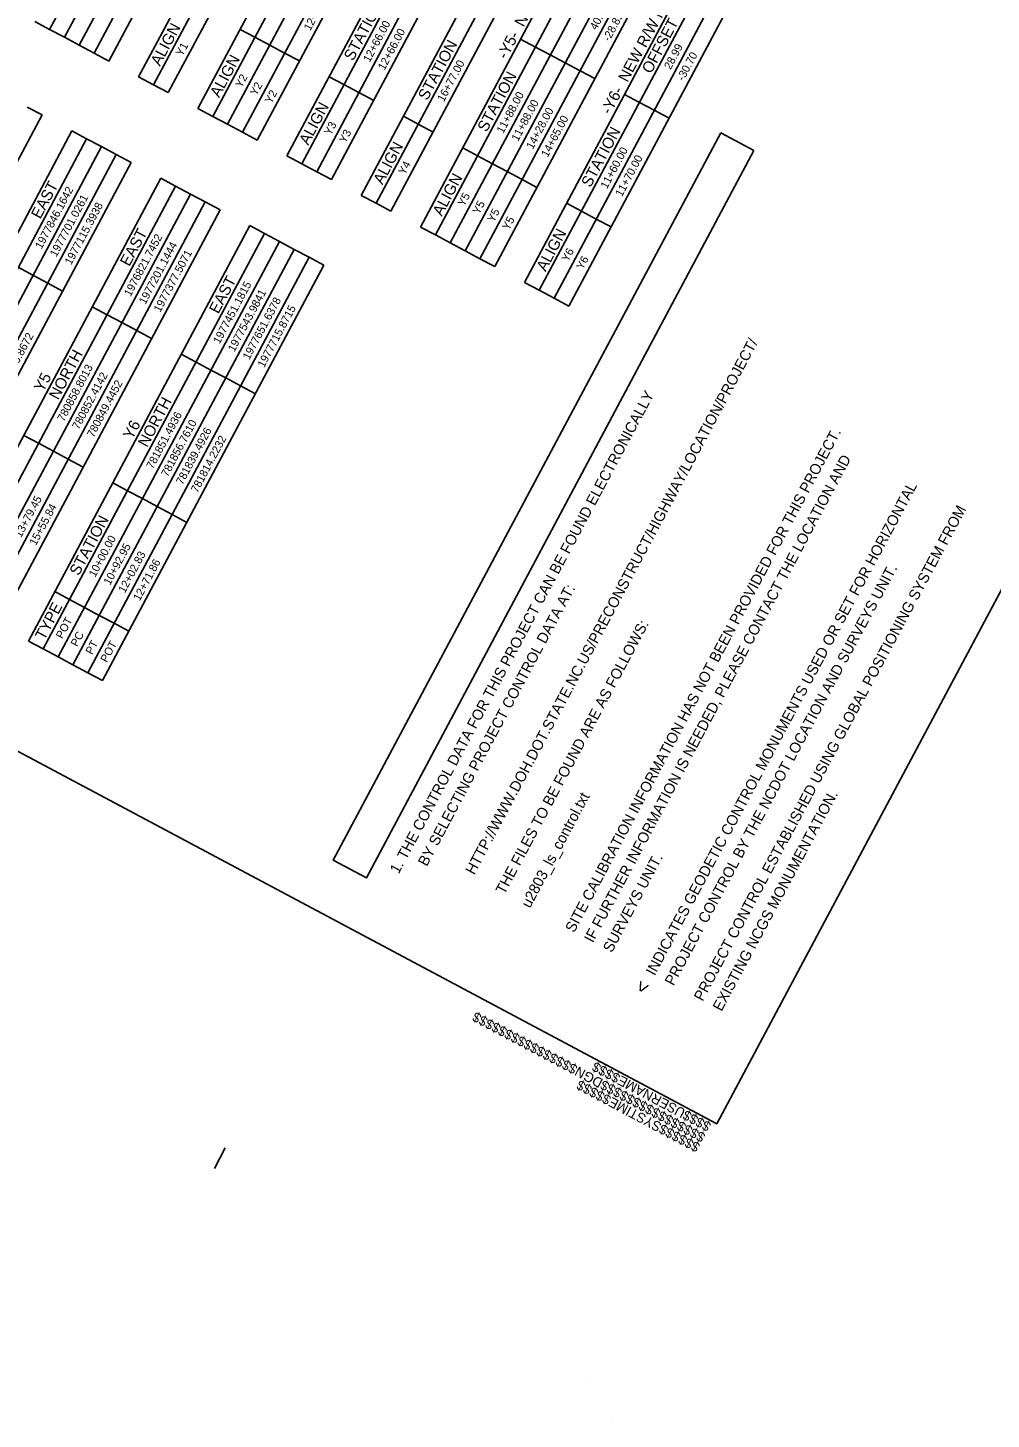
# Model space of a CAD drawing. Extents: x 1979034 to 1987549, y 771535 to 781988.
# Drawn here: x 1981933 to 1984640, y 771535 to 775446 of the extents above; entities that cross this region are included whole.
import ezdxf

# ---------------------------------------------------------------- set-up
doc = ezdxf.new("R2010")
doc.units = 0
for name, color, linetype in [('CTL Sheet Border CELL', 7, 'Continuous'), ('CTL Sheet Notes CELL', 7, 'Continuous'), ('CTL Sheet Table Cell', 7, 'Continuous'), ('CTL Sheet Text', 7, 'Continuous'), ('Old_Level_2', 7, 'Continuous'), ('Old_Level_57', 7, 'Continuous'), ('Sheet Data Field CELL', 7, 'Continuous')]:
    doc.layers.add(name, color=color, linetype=linetype)

msp = doc.modelspace()

# ---------------------------------------------------------------- linework, layer by layer
at = {"layer": 'CTL Sheet Border CELL'}
msp.add_lwpolyline([(1982714.7, 781848.1), (1979034.2, 774941.4), (1983868.8, 772365.1), (1987549.3, 779271.7)], close=True, dxfattribs=at)
for points in [[(1983973.6, 775100.4), (1982884.2, 773056), (1982790.5, 773105.7), (1983880, 775150.2)], [(1983880, 775150.2), (1983973.6, 775100.4)]]:
    msp.add_lwpolyline(points, dxfattribs=at)
at = {"layer": 'CTL Sheet Table Cell'}
for p, q in [((1981993.9, 775441.2), (1982823.5, 776997.9)), ((1982035.6, 775418.9), (1982865.2, 776975.7)), ((1982077.3, 775396.7), (1982906.9, 776953.5)), ((1982119, 775374.5), (1982948.6, 776931.3)), ((1982160.7, 775352.3), (1982990.3, 776909)), ((1982244.1, 775307.8), (1983073.7, 776864.6)), ((1982285.8, 775285.6), (1983115.4, 776842.4)), ((1982327.5, 775263.4), (1983157.1, 776820.1)), ((1982410.9, 775218.9), (1983240.5, 776775.7)), ((1982452.6, 775196.7), (1983282.2, 776753.5)), ((1982494.3, 775174.5), (1983323.9, 776731.3)), ((1982536, 775152.3), (1983365.5, 776709)), ((1982577.7, 775130.1), (1983407.2, 776686.8)), ((1982661.1, 775085.6), (1983490.6, 776642.4)), ((1982702.8, 775063.4), (1983532.3, 776620.2)), ((1982744.5, 775041.2), (1983574, 776597.9)), ((1982786.2, 775019), (1983615.7, 776575.7)), ((1982869.6, 774974.5), (1983699.1, 776531.3)), ((1982911.3, 774952.3), (1983740.8, 776509.1)), ((1982953, 774930.1), (1983782.5, 776486.8)), ((1983036.3, 774885.6), (1983865.9, 776442.4)), ((1983078, 774863.4), (1983907.6, 776420.2)), ((1983119.7, 774841.2), (1983949.3, 776397.9)), ((1983161.4, 774819), (1983991, 776375.7)), ((1983203.1, 774796.7), (1984032.7, 776353.5)), ((1983244.8, 774774.5), (1984074.4, 776331.3)), ((1983328.2, 774730.1), (1984157.8, 776286.8)), ((1983369.9, 774707.9), (1984199.5, 776264.6)), ((1983411.6, 774685.6), (1984241.2, 776242.4)), ((1983453.3, 774663.4), (1984282.9, 776220.2)), ((1981952.2, 775463.4), (1981993.9, 775441.2)), ((1981993.9, 775441.2), (1982035.6, 775418.9)), ((1982035.6, 775418.9), (1982077.3, 775396.7)), ((1982529.4, 775441.3), (1982571.1, 775419.1)), ((1982571.1, 775419.1), (1982612.8, 775396.9)), ((1982077.3, 775396.7), (1982119, 775374.5)), ((1982612.8, 775396.9), (1982654.5, 775374.7)), ((1983317.8, 775413.8), (1983359.5, 775391.6)), ((1983359.5, 775391.6), (1983401.2, 775369.4)), ((1982119, 775374.5), (1982160.7, 775352.3)), ((1982654.5, 775374.7), (1982696.2, 775352.5)), ((1983401.2, 775369.4), (1983442.9, 775347.2)), ((1983442.9, 775347.2), (1983484.6, 775324.9)), ((1982244.1, 775307.8), (1982285.8, 775285.6)), ((1982779.6, 775308), (1982821.3, 775285.8)), ((1983484.6, 775324.9), (1983526.3, 775302.7)), ((1982285.8, 775285.6), (1982327.5, 775263.4)), ((1982821.3, 775285.8), (1982863, 775263.6)), ((1982863, 775263.6), (1982904.7, 775241.4)), ((1981931, 775222.8), (1981972.7, 775200.6)), ((1983609.7, 775258.3), (1983651.4, 775236)), ((1983651.4, 775236), (1983693.1, 775213.8)), ((1981350.6, 774033), (1981972.7, 775200.6)), ((1982410.9, 775218.9), (1982452.6, 775196.7)), ((1982452.6, 775196.7), (1982494.3, 775174.5)), ((1982988.1, 775196.9), (1983029.8, 775174.7)), ((1983693.1, 775213.8), (1983734.8, 775191.6)), ((1981434, 773988.6), (1982056.1, 775156.1)), ((1982056.1, 775156.1), (1982097.8, 775133.9)), ((1982494.3, 775174.5), (1982536, 775152.3)), ((1982536, 775152.3), (1982577.7, 775130.1)), ((1983029.8, 775174.7), (1983071.5, 775152.5)), ((1981475.7, 773966.3), (1982097.8, 775133.9)), ((1981517.4, 773944.1), (1982139.5, 775111.7)), ((1982097.8, 775133.9), (1982139.5, 775111.7)), ((1982139.5, 775111.7), (1982181.2, 775089.5)), ((1983154.9, 775108), (1983196.6, 775085.8)), ((1981559.1, 773921.9), (1982181.2, 775089.5)), ((1981600.8, 773899.7), (1982222.9, 775067.2)), ((1982181.2, 775089.5), (1982222.9, 775067.2)), ((1982661.1, 775085.6), (1982702.8, 775063.4)), ((1983196.6, 775085.8), (1983238.3, 775063.6)), ((1982702.8, 775063.4), (1982744.5, 775041.2)), ((1982744.5, 775041.2), (1982786.2, 775019)), ((1983238.3, 775063.6), (1983280, 775041.4)), ((1983280, 775041.4), (1983321.7, 775019.1)), ((1981684.1, 773855.2), (1982306.3, 775022.8)), ((1981725.8, 773833), (1982348, 775000.6)), ((1982306.3, 775022.8), (1982348, 775000.6)), ((1982348, 775000.6), (1982389.7, 774978.4)), ((1983321.7, 775019.1), (1983363.4, 774996.9)), ((1981767.5, 773810.8), (1982389.7, 774978.4)), ((1981809.2, 773788.6), (1982431.4, 774956.1)), ((1982389.7, 774978.4), (1982431.4, 774956.1)), ((1982431.4, 774956.1), (1982473.1, 774933.9)), ((1982869.6, 774974.5), (1982911.3, 774952.3)), ((1982911.3, 774952.3), (1982953, 774930.1)), ((1983446.8, 774952.5), (1983488.5, 774930.3)), ((1981850.9, 773766.3), (1982473.1, 774933.9)), ((1983488.5, 774930.3), (1983530.2, 774908)), ((1983530.2, 774908), (1983571.8, 774885.8)), ((1981934.3, 773721.9), (1982556.5, 774889.5)), ((1982556.5, 774889.5), (1982598.2, 774867.2)), ((1983036.3, 774885.6), (1983078, 774863.4)), ((1981976, 773699.7), (1982598.2, 774867.2)), ((1982017.7, 773677.5), (1982639.9, 774845)), ((1982598.2, 774867.2), (1982639.9, 774845)), ((1982639.9, 774845), (1982681.6, 774822.8)), ((1983078, 774863.4), (1983119.7, 774841.2)), ((1983119.7, 774841.2), (1983161.4, 774819)), ((1982059.4, 773655.2), (1982681.6, 774822.8)), ((1982101.1, 773633), (1982723.3, 774800.6)), ((1982681.6, 774822.8), (1982723.3, 774800.6)), ((1982723.3, 774800.6), (1982765, 774778.4)), ((1983161.4, 774819), (1983203.1, 774796.7)), ((1983203.1, 774796.7), (1983244.8, 774774.5)), ((1981905.3, 774772.5), (1981947, 774750.3)), ((1982142.8, 773610.8), (1982765, 774778.4)), ((1981947, 774750.3), (1981988.7, 774728.1)), ((1981988.7, 774728.1), (1982030.4, 774705.8)), ((1983328.2, 774730.1), (1983369.9, 774707.9)), ((1983369.9, 774707.9), (1983411.6, 774685.6)), ((1983411.6, 774685.6), (1983453.3, 774663.4)), ((1982113.8, 774661.4), (1982155.5, 774639.2)), ((1982155.5, 774639.2), (1982197.2, 774617)), ((1982197.2, 774617), (1982238.9, 774594.7)), ((1982238.9, 774594.7), (1982280.5, 774572.5)), ((1982363.9, 774528.1), (1982405.6, 774505.9)), ((1982405.6, 774505.9), (1982447.3, 774483.6)), ((1982447.3, 774483.6), (1982489, 774461.4)), ((1982489, 774461.4), (1982530.7, 774439.2)), ((1982530.7, 774439.2), (1982572.4, 774417)), ((1981921.2, 774300), (1981962.9, 774277.8)), ((1981962.9, 774277.8), (1982004.6, 774255.6)), ((1982004.6, 774255.6), (1982046.3, 774233.4)), ((1982046.3, 774233.4), (1982088, 774211.1)), ((1982171.4, 774166.7), (1982213.1, 774144.5)), ((1982213.1, 774144.5), (1982254.8, 774122.2)), ((1982254.8, 774122.2), (1982296.5, 774100)), ((1982296.5, 774100), (1982338.2, 774077.8)), ((1982338.2, 774077.8), (1982379.9, 774055.6)), ((1982008.4, 773860.9), (1982050.1, 773838.7)), ((1982050.1, 773838.7), (1982091.8, 773816.5)), ((1982091.8, 773816.5), (1982133.5, 773794.2)), ((1982133.5, 773794.2), (1982175.2, 773772)), ((1982175.2, 773772), (1982216.9, 773749.8)), ((1981934.3, 773721.9), (1981976, 773699.7)), ((1981976, 773699.7), (1982017.7, 773677.5)), ((1982017.7, 773677.5), (1982059.4, 773655.2)), ((1982059.4, 773655.2), (1982101.1, 773633)), ((1982101.1, 773633), (1982142.8, 773610.8))]:
    msp.add_line(p, q, dxfattribs=at)
at = {"layer": 'Sheet Data Field CELL'}
for p, q in [((1982456.9, 772239.6), (1982487.6, 772297.1)), ((1983502.7, 771649.7), (1983502.7, 771649.7)), ((1983574.1, 771534.8), (1983574.1, 771534.8))]:
    msp.add_line(p, q, dxfattribs=at)

# ---------------------------------------------------------------- texts
at = {"layer": 'CTL Sheet Notes CELL'}
for s, p in [('-Y5-  NEW R/W MONUMENTS', (1983277.6, 775355.1)), ('-Y6-  NEW R/W MONUMENTS', (1983569.5, 775199.6)), ('STATION', (1982846.8, 775350.5)), ('ALIGN', (1982303.8, 775336.2)), ('OFFSET', (1983684.3, 775314.5)), ('STATION', (1983055.3, 775239.4)), ('ALIGN', (1982470.6, 775247.3)), ('STATION', (1983222.1, 775150.5)), ('ALIGN', (1982720.8, 775113.9)), ('STATION', (1983514, 774994.9)), ('ALIGN', (1982929.3, 775002.8)), ('ALIGN', (1983096.1, 774914)), ('EAST', (1981967.7, 774906.3)), ('EAST', (1982217.8, 774773)), ('ALIGN', (1983388, 774758.4)), ('EAST', (1982468, 774639.7)), ('NORTH', (1982017.9, 774397.8)), ('Y5', (1981976, 774419.7)), ('NORTH', (1982268.1, 774264.5)), ('Y6', (1982226.2, 774286.4)), ('STATION', (1982075.6, 773903.3)), ('TYPE', (1981979.2, 773722.3))]:
    msp.add_text(s, height=31.5, rotation=61.9471, dxfattribs=at).set_placement(p)
at = {"layer": 'CTL Sheet Text'}
for s, p in [('12+84.24', (1982726.5, 775435.7)), ('40.00', (1983530.7, 775437.7)), ('12+66.00', (1982893.3, 775346.8)), ('-28.89', (1983567.1, 775405.6)), ('12+66.00', (1982935, 775324.6)), ('Y1', (1982367.1, 775364)), ('28.99', (1983739.2, 775326.6)), ('16+77.00', (1983101.8, 775235.7)), ('-30.70', (1983775.6, 775294.5)), ('Y2', (1982533.9, 775275.1)), ('Y2', (1982575.6, 775252.9)), ('Y2', (1982617.2, 775230.7)), ('11+88.00', (1983268.6, 775146.8)), ('11+88.00', (1983310.3, 775124.6)), ('14+28.00', (1983352, 775102.3)), ('Y3', (1982784, 775141.8)), ('14+65.00', (1983393.7, 775080.1)), ('Y3', (1982825.7, 775119.6)), ('11+60.00', (1983560.5, 774991.2)), ('Y4', (1982992.5, 775030.7)), ('11+70.00', (1983602.2, 774969)), ('1977846.1642', (1981971.1, 774821.9)), ('1977701.0261', (1982012.8, 774799.7)), ('1977115.3938', (1982054.5, 774777.4)), ('Y5', (1983159.3, 774941.8)), ('Y5', (1983201, 774919.6)), ('Y5', (1983242.7, 774897.3)), ('Y5', (1983284.4, 774875.1)), ('1976821.7452', (1982221.3, 774688.6)), ('1977201.1444', (1982263, 774666.3)), ('1977377.5071', (1982304.7, 774644.1)), ('Y6', (1983451.2, 774786.2)), ('Y6', (1983492.9, 774764)), ('1977451.1815', (1982471.5, 774555.2)), ('1977543.9841', (1982513.2, 774533)), ('1977651.6378', (1982554.9, 774510.8)), ('1977715.8715', (1982596.6, 774488.6)), ('780286.8672', (1981867.2, 774425.9)), ('780858.8013', (1982033.9, 774337)), ('780852.4142', (1982075.6, 774314.8)), ('780849.4452', (1982117.3, 774292.6)), ('781851.4936', (1982284.1, 774203.7)), ('781856.7610', (1982325.8, 774181.5)), ('781839.4926', (1982367.5, 774159.3)), ('781814.2232', (1982409.2, 774137)), ('13+79.45', (1981913.6, 774010.8)), ('15+55.84', (1981955.3, 773988.5)), ('10+00.00', (1982122.1, 773899.7)), ('10+92.95', (1982163.8, 773877.4)), ('12+02.83', (1982205.5, 773855.2)), ('12+71.86', (1982247.2, 773833)), ('POT', (1982029.9, 773726.5)), ('PC ', (1982071.6, 773704.3)), ('PT ', (1982113.3, 773682.1)), ('POT', (1982155, 773659.8))]:
    msp.add_text(s, height=22.5, rotation=61.9471, dxfattribs=at).set_placement(p)
at = {"layer": 'Old_Level_2'}
for s, rotation, p in [('HTTP://WWW.DOH.DOT.STATE.NC.US/PRECONSTRUCT/HIGHWAY/LOCATION/PROJECT/', 61.9471, (1983187.1, 773063.1)), ('1. THE CONTROL DATA FOR THIS PROJECT CAN BE FOUND ELECTRONICALLY', 61.9471, (1982974.8, 773065.6)), ('SITE CALIBRATION INFORMATION HAS NOT BEEN PROVIDED FOR THIS PROJECT.', 61.9471, (1983467.9, 772900.2)), ('IF FURTHER INFORMATION IS NEEDED, PLEASE CONTACT THE LOCATION AND', 61.9471, (1983520.9, 772872)), ('INDICATES GEODETIC CONTROL MONUMENTS USED OR SET FOR HORIZONTAL', 61.8418, (1983694.5, 772779.4)), ('PROJECT CONTROL ESTABLISHED USING GLOBAL POSITIONING SYSTEM FROM', 61.8418, (1983829.4, 772707.5)), ('PROJECT CONTROL BY THE NCDOT LOCATION AND SURVEYS UNIT.', 61.8418, (1983747.4, 772751.1)), ('     BY SELECTING PROJECT CONTROL DATA AT:', 61.9471, (1983027.8, 773037.4)), ('THE FILES TO BE FOUND ARE AS FOLLOWS:', 61.9471, (1983272.2, 773007.6)), ('u2803_ls_control.txt', 61.9471, (1983343.9, 772969.4)), ('EXISTING NCGS MONUMENTATION.', 61.8418, (1983882.3, 772679.2)), ('SURVEYS UNIT.', 61.9471, (1983573.8, 772843.8))]:
    msp.add_text(s, height=30, rotation=rotation, dxfattribs=at).set_placement(p)
at = {"layer": 'Old_Level_57'}
msp.add_text('>', height=39.1, rotation=241.9613, dxfattribs=at).set_placement((1983650.8, 772771.2))
at = {"layer": 'Sheet Data Field CELL'}
for s, p in [('$$$$$$$$$$$$$$$$DGN$$$$$$$$$$$$$$$$', (1983839.2, 772335.7)), ('$$$$USERNAME$$$$', (1983855.3, 772366)), ('$$$$$$SYSTIME$$$$$', (1983824.4, 772307.9))]:
    msp.add_text(s, height=27.391, rotation=151.9471, dxfattribs=at).set_placement(p)

doc.saveas('drawing.dxf')
